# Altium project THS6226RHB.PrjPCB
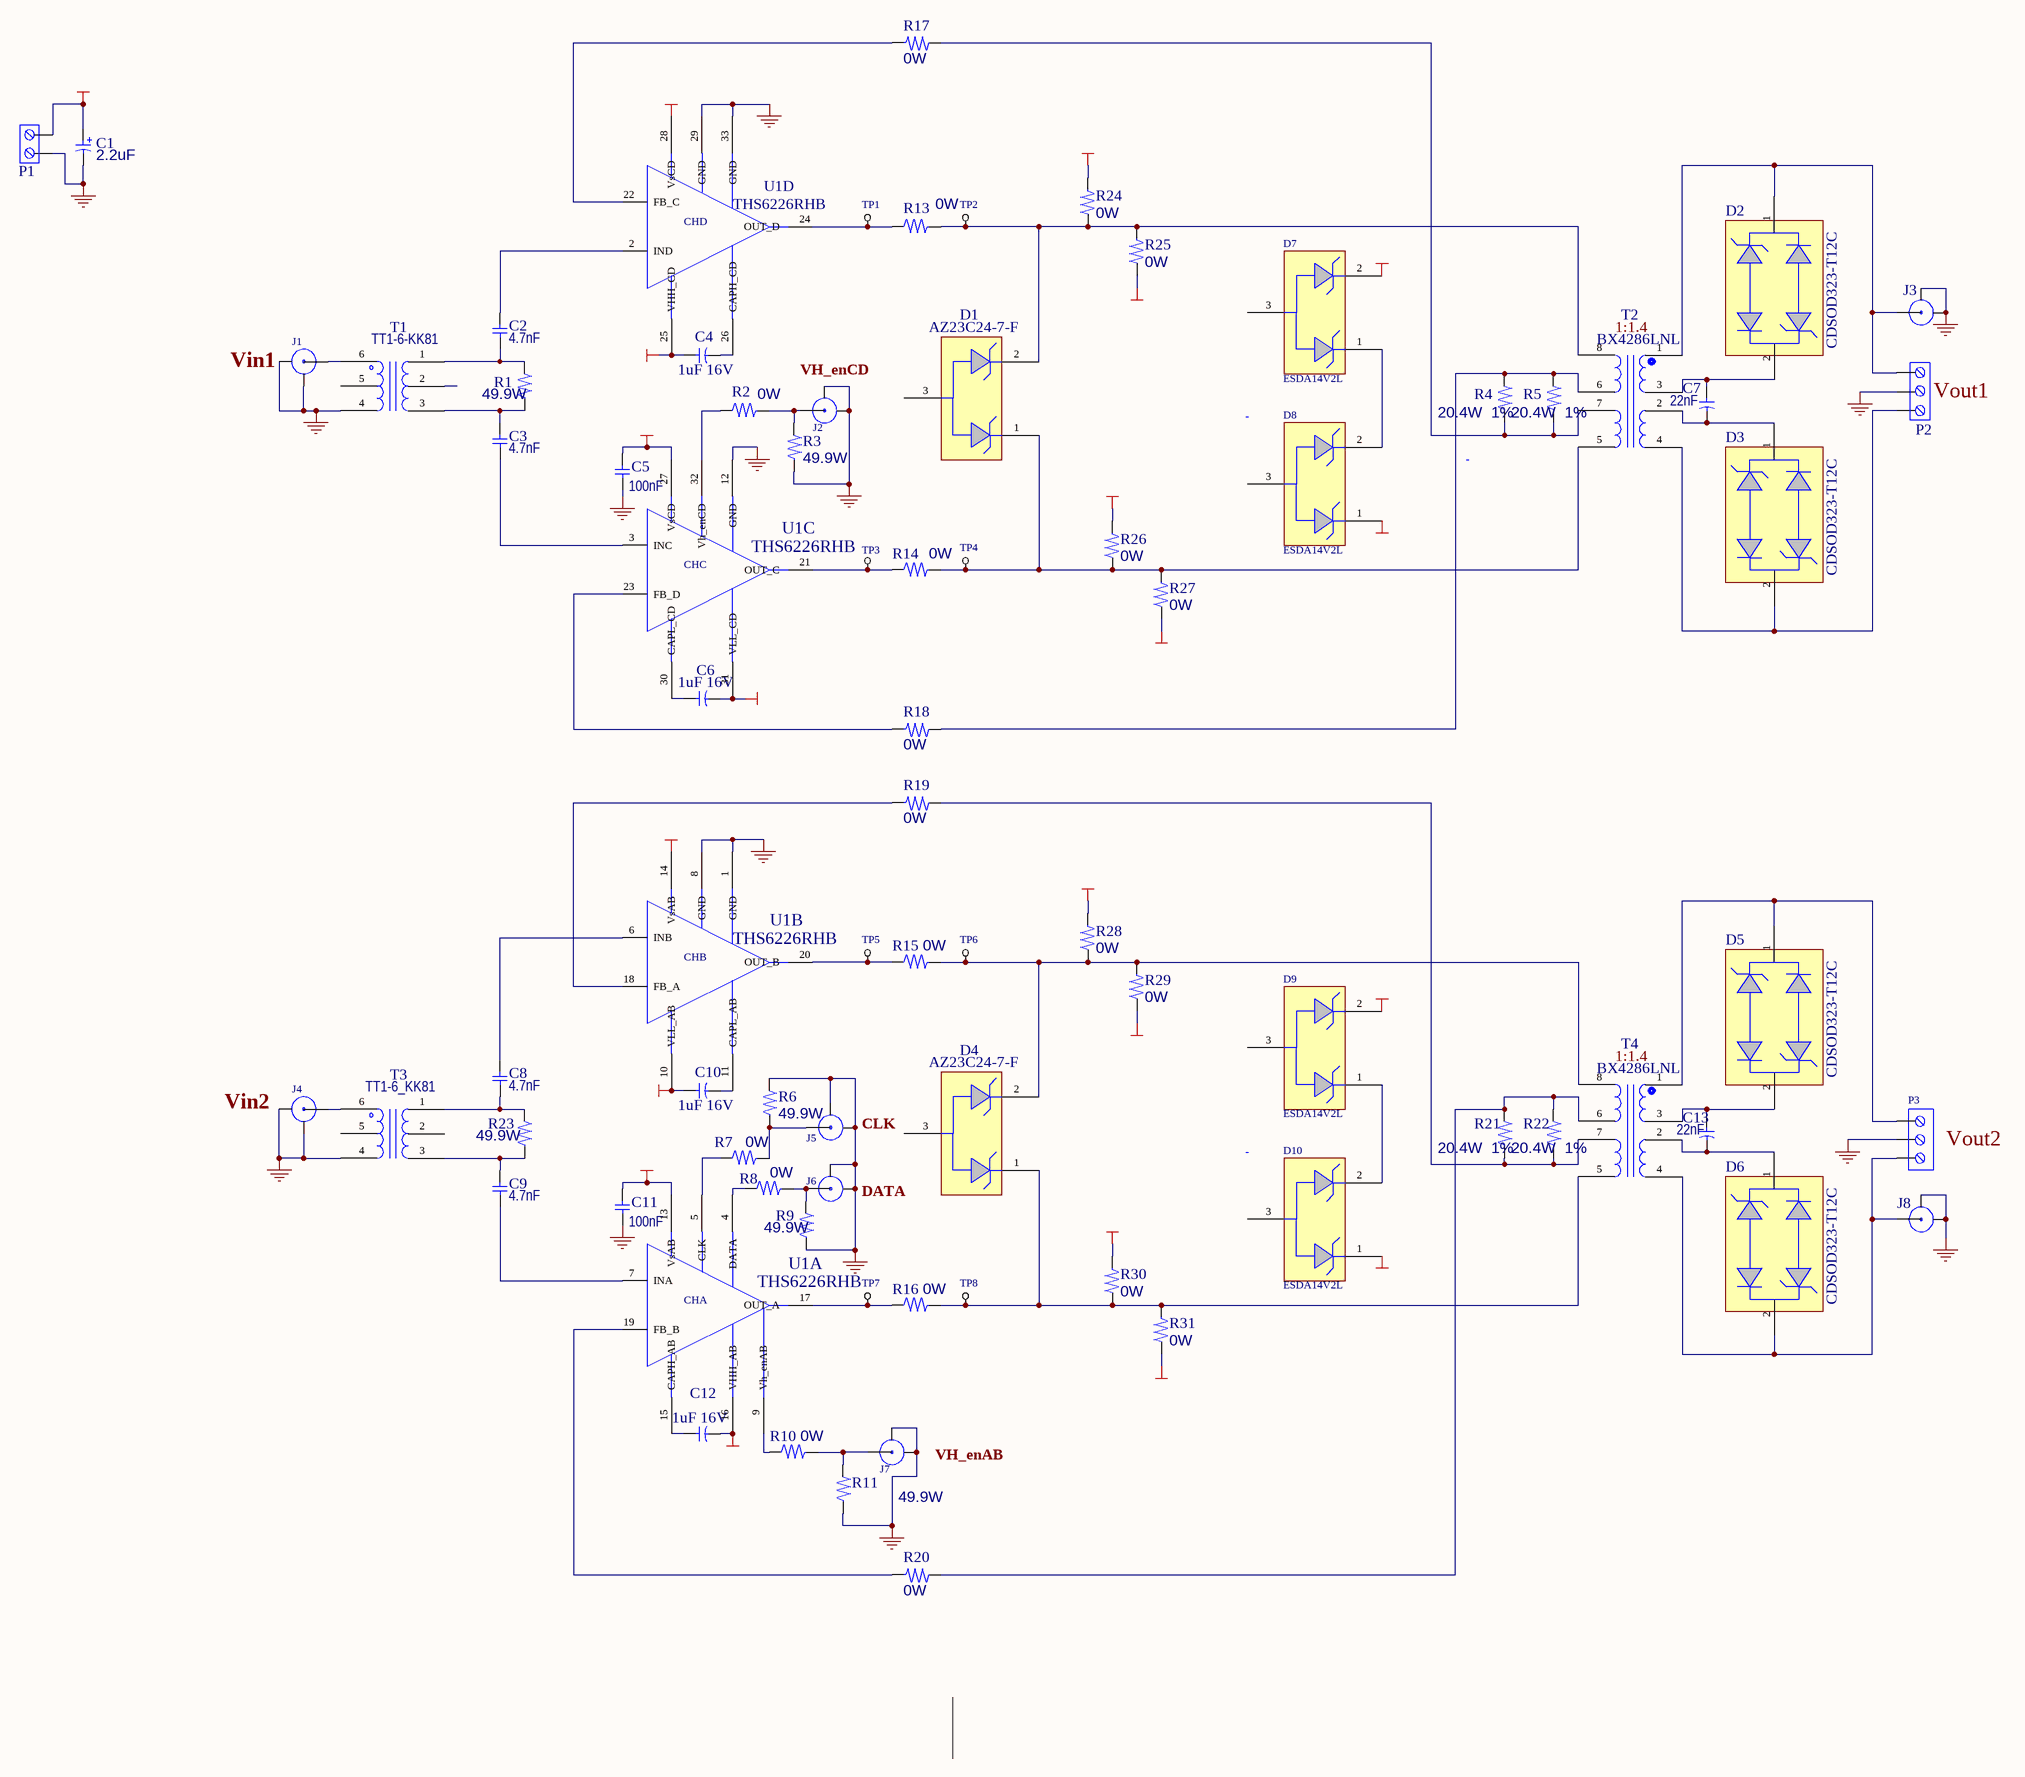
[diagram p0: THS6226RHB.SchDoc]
1 sheet, 77 parts. Net scope: global (net labels, ports and power ports of the same name join across sheets).
Board file: THS6226RHB.PcbDoc

## Sheet THS6226RHB.SchDoc: THS6226RHB _Test_PCB_Single
size C; Date: 10-06-2010; CompanyName: Texas Instruments, Inc.; DrawnBy: Phung Luong; Engineer: Xavier Ramus; Address1: Texas Instruments; Address2: 5411 E Williams Blvd.; Address3: Tucson, AZ 85711; Address4: U.S.A.; DocumentNumber: PR1980; Revision: A; SheetNumber: 1; SheetTotal: 1; PageSetup: Record=PageOptions|CenterHorizontal=True|CenterVertical=True|PrintScale=0.76|XCorrection=1.00|YCorrection=1.00|PrintKind=2|BorderSize=5000000|LeftOffset=0|BottomOffset=0|Orientation=2|PaperLength=1000|PaperWidth=1000|Scale=100|PaperSource=15|PrintQuality=600|MediaType=1|DitherType=10|PaperKind=Letter|PrintScaleMode=1

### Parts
C1  2.2uF  [3216]
C2  4.7nF  [0805]
C3  4.7nF  [0805]
C4  1uF 16V  [C402]
C5  100nF  [C402]
C6  1uF 16V  [C402]
C7  22nF  [1210]
C8  4.7nF  [0805]
C9  4.7nF  [0805]
C10  1uF 16V  [C402]
C11  100nF  [C402]
C12  1uF 16V  [C402]
C13  22nF  [1210]
D1  AZ23C24-7-F  [SOT23-2]
D2  CDSOD323-T12C  [SOD-323]
D3  CDSOD323-T12C  [SOD-323]
D4  AZ23C24-7-F  [SOT23-2]
D5  CDSOD323-T12C  [SOD-323]
D6  CDSOD323-T12C  [SOD-323]
D7  ESDA14V2L  [SOT23-2]
D8  ESDA14V2L  [SOT23-2]
D9  ESDA14V2L  [SOT23-2]
D10  ESDA14V2L  [SOT23-2]
J1  Vin1  [SMA - Surface mount]
J2  VH_enCD  [SMA - Surface mount]
J3  Vout1  [SMA - Surface mount]
J4  Vin2  [SMA - Surface mount]
J5  CLK  [SMA - Surface mount]
J6  DATA  [SMA - Surface mount]
J7  VH_enAB  [SMA - Surface mount]
J8  Vout2  [SMA - Surface mount]
P1  TERMINAL BLOCK 2  [Term Block 2 pins 5mm]  (value not drawn)
P2  TERMINAL BLOCK 3  [TERMINAL BLOCK 3]  (value not drawn)
P3  TERMINAL BLOCK 3  [TERMINAL BLOCK 3 pins 5mm]  (value not drawn)
R1  49.9W  [0805]
R2  0W  [0603]
R3  49.9W  [0603]
R4  20.4W  1%  [1206]
R5  20.4W  1%  [1206]
R6  49.9W  [0603]
R7  0W  [0603]
R8  0W  [0603]
R9  49.9W  [0603]
R10  0W  [0603]
R11  49.9W  [0603]
R13  0W  [0402]
R14  0W  [0402]
R15  0W  [0402]
R16  0W  [0402]
R17  0W  [0402]
R18  0W  [0402]
R19  0W  [0402]
R20  0W  [0402]
R21  20.4W  1%  [1206]
R22  20.4W  1%  [1206]
R23  49.9W  [0805]
R24  0W  [0603]
R25  0W  [0603]
R26  0W  [0603]
R27  0W  [0603]
R28  0W  [0603]
R29  0W  [0603]
R30  0W  [0603]
R31  0W  [0603]
T1  TT1-6-KK81  [TT1-6-KK81]
T2  BX4286LNL  [BX4246_BX4286LNL]
T3  TT1-6_KK81  [TT1-6-KK81]
T4  BX4286LNL  [BX4246_BX4286LNL]
TP1  TEST POINT  [TP1]  (value not drawn)
TP2  TEST POINT  [TP1]  (value not drawn)
TP3  TEST POINT  [TP1]  (value not drawn)
TP4  TEST POINT  [TP1]  (value not drawn)
TP5  TEST POINT  [TP1]  (value not drawn)
TP6  TEST POINT  [TP1]  (value not drawn)
TP7  TEST POINT  [TP1]  (value not drawn)
TP8  TEST POINT  [TP1]  (value not drawn)
U1  THS6226RHB  [QFN 5.15X5.15 (32 PIN) RHB]  (parts A,B,C,D of 4)

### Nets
+12V: C1.1 C5.1 C11.1 P1.1 U1.13(VsAB) U1.14(VsAB) U1.27(VsCD) U1.28(VsCD)
GND: C1.2 C5.2 C11.2 J1.1 J1.3 J2.1 J2.3 J3.1 J3.3 J4.1 J4.3 J5.1 J5.3 J6.1 J6.3 J7.1 J7.3 J8.1 J8.3 P1.2 P2.2 P3.2 R3.2 R6.1 R9.2 R11.2 T1.4 T3.4 U1.1(GND) U1.8(GND) U1.12(GND) U1.29(GND) U1.33(GND)
VHH_AB: C10.1 D9.2 R28.2 R30.2 U1.10(VLL_AB)
VHH_CD: C4.1 D7.2 R24.2 R26.2 U1.25(VHH_CD)
VLL_AB: C12.2 D10.1 R29.1 R31.1 U1.16(VHH_AB)
VLL_CD: C6.2 D8.1 R25.1 R27.1 U1.31(VLL_CD)
NetC2_1: C2.1 U1.2(IND)
NetC2_2: C2.2 R1.1 T1.1
NetC3_1: C3.1 R1.2 T1.3
NetC3_2: C3.2 U1.3(INC)
NetC4_2: C4.2 U1.26(CAPH_CD)
NetC6_1: C6.1 U1.30(CAPL_CD)
NetC7_1: C7.1 D2.2 T2.3
NetC7_2: C7.2 D3.1 T2.2
NetC8_1: C8.1 U1.6(INB)
NetC8_2: C8.2 R23.1 T3.1
NetC9_1: C9.1 R23.2 T3.3
NetC9_2: C9.2 U1.7(INA)
NetC10_2: C10.2 U1.11(CAPL_AB)
NetC12_1: C12.1 U1.15(CAPH_AB)
NetC13_1: C13.1 D5.2 T4.3
NetC13_2: C13.2 D6.1 T4.2
NetD1_1: D1.1 R14.2 R26.1 R27.2 T2.5 TP4.1(TP)
NetD1_2: D1.2 R13.2 R24.1 R25.2 T2.8 TP2.1(TP)
NetD2_1: D2.1 J3.2 P2.1 T2.1
NetD3_2: D3.2 P2.3 T2.4
NetD4_1: D4.1 R16.2 R30.1 R31.2 T4.5 TP8.1(TP)
NetD4_2: D4.2 R15.2 R28.1 R29.2 T4.8 TP6.1(TP)
NetD5_1: D5.1 P3.3 T4.1
NetD6_2: D6.2 J8.2 P3.1 T4.4
NetD7_1: D7.1 D8.2
NetD9_1: D9.1 D10.2
NetJ1_2: J1.2 T1.6
NetJ2_2: J2.2 R2.2 R3.1
NetJ4_2: J4.2 T3.6
NetJ5_2: J5.2 R6.2 R7.2
NetJ6_2: J6.2 R8.2 R9.1
NetJ7_2: J7.2 R10.2 R11.1
NetR2_1: R2.1 U1.32(Vh_enCD)
NetR4_1: R4.1 R5.1 R18.1 T2.6
NetR4_2: R4.2 R5.2 R17.1 T2.7
NetR7_1: R7.1 U1.5(CLK)
NetR8_1: R8.1 U1.4(DATA)
NetR10_1: R10.1 U1.9(Vh_enAB)
NetR13_1: R13.1 TP1.1(TP) U1.24(OUT_D)
NetR14_1: R14.1 TP3.1(TP) U1.21(OUT_C)
NetR15_1: R15.1 TP5.1(TP) U1.20(OUT_B)
NetR16_1: R16.1 TP7.1(TP) U1.17(OUT_A)
NetR17_2: R17.2 U1.22(FB_C)
NetR18_2: R18.2 U1.23(FB_D)
NetR19_1: R19.1 R21.2 R22.2 T4.7
NetR19_2: R19.2 U1.18(FB_A)
NetR20_1: R20.1 R21.1 R22.1 T4.6
NetR20_2: R20.2 U1.19(FB_B)

Not connected (* = marked no-connect by the designer): D1 3; D4 3; D7 3; D8 3; D9 3; D10 3; T1 2 5; T3 2 5

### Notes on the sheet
- (near T2) 1:1.4
- (near T4) 1:1.4

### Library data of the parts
C1 = CAP (Polarized SM)
C2 C3 C5 C8 C9 C11 = CAP
C4 C6 C7 C10 C12 C13 = CAP (SM)
D1 D4 D7-D10 = SOT23 DBV_3PINS
D2 D3 D5 D6 = SOD-323 (BIDIRECTIONAL)
J1-J8 = SMA JACK
P1 = TERMINAL BLOCK 2: 2 CONTACT TERMINAL BLOCK
P2 P3 = TERMINAL BLOCK 3: 3 CONTACT TERMINAL BLOCK
R1-R11 R13-R31 = RES (SM)
T2 T4 = BX4246LNL: Manufacturer: Pulse
T3 = TT1-6-KK81
TP1-TP8 = TEST POINT: Part No: M2551-2-00-01-00-00-07-0; Manufacturer: Mill Max
U1 = THS6224RHB: Dual Port , Differential VDSL Line Driver Amplifiers; Part No: THS6184PWPR; Manufacturer: Texas Instruments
